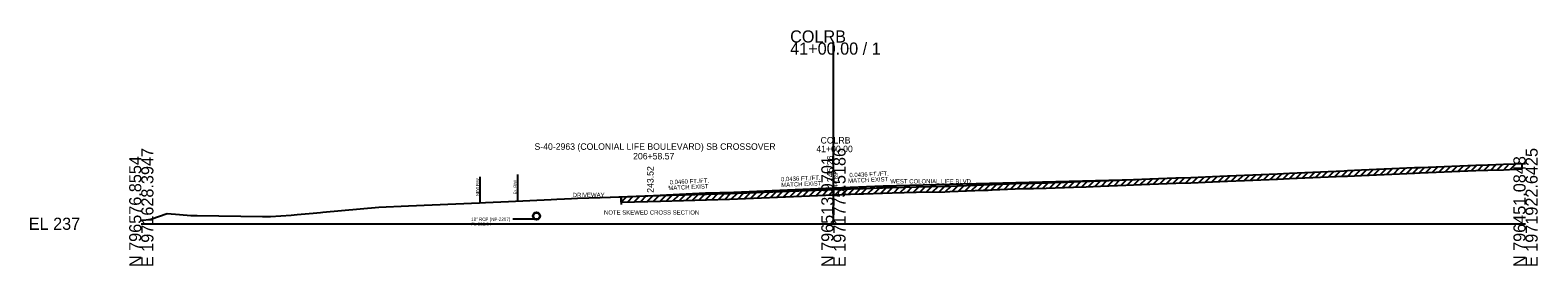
# Model space of a CAD drawing. Extents: x -26 to 1971766, y -10 to 796432.
# Drawn here: x -25.7 to 322.8, y 5490.3 to 5544.7 of the extents above; entities that cross this region are included whole.
import ezdxf

# ---------------------------------------------------------------- set-up
doc = ezdxf.new("R2010")
doc.units = 0
for name, color, linetype in [('BR_AUTO DIMENSION', 7, 'Continuous'), ('BR_BORDER LINES', 7, 'Continuous'), ('BR_CENTER LINE BASELINE', 7, 'Continuous'), ('BR_CONCRETE', 7, 'Continuous'), ('BR_TABLE LINES', 7, 'Continuous'), ('Level 31', 7, 'Continuous'), ('MISCELLANEOUS', 7, 'Continuous'), ('North Arrow', 7, 'Continuous'), ('RD_HC_CL_Rel', 7, 'Continuous'), ('RD_PD_ALT2_TnTmp', 7, 'Continuous'), ('RD_PD_CstnLmt', 7, 'Continuous'), ('RD_PD_FOC', 7, 'Continuous'), ('RD_PD_MedBWall', 7, 'Continuous'), ('RD_PD_WallFill', 7, 'Continuous'), ('RD_SHT_IplotShp', 7, 'Continuous')]:
    doc.layers.add(name, color=color, linetype=linetype)

msp = doc.modelspace()

# ---------------------------------------------------------------- linework, layer by layer
at = {"layer": 'BR_AUTO DIMENSION'}
for p, q in [((160, 5500), (160, 5541.81)), ((0, 5500), (160, 5500)), ((160, 5500), (320, 5500))]:
    msp.add_line(p, q, dxfattribs=at)
at = {"layer": 'BR_BORDER LINES'}
msp.add_lwpolyline([(0, 5500.79), (2.17, 5501.04), (6.01, 5502.35), (8.85, 5502.13), (11.47, 5501.89), (12.93, 5501.87), (28.02, 5501.69), (28.61, 5501.7), (29.89, 5501.7), (34.65, 5502), (36.03, 5502.11), (39.71, 5502.46), (41.42, 5502.59), (41.96, 5502.64), (54.91, 5503.82), (61.76, 5504.11), (78.16, 5504.83), (79.56, 5504.9), (84.88, 5505.14), (94.78, 5505.58), (96.06, 5505.65), (97.83, 5505.75), (99.44, 5505.83), (100.82, 5505.89), (106.04, 5506.05), (110.94, 5506.25), (117.06, 5506.42), (119.99, 5506.5), (135.94, 5506.95), (160, 5507.89), (165.93, 5508.12), (166.51, 5508.15), (166.96, 5508.17), (173.59, 5508.4), (179.16, 5508.51), (185.72, 5508.65), (186.9, 5508.69), (194.62, 5508.99), (195.79, 5509.04), (196.66, 5509.08), (203.77, 5509.36), (206.24, 5509.4), (209.18, 5509.47), (215.48, 5509.71), (218.45, 5509.8), (221.72, 5509.92), (227.57, 5510.15), (229.33, 5510.23), (233.15, 5510.35), (239.13, 5510.59), (242.65, 5510.7), (249.35, 5510.98), (251.06, 5511.04), (255.04, 5511.24), (262.63, 5511.55), (265.41, 5511.7), (274.39, 5512.07), (278.1, 5512.22), (278.86, 5512.26), (282.07, 5512.41), (294.35, 5512.95), (295.65, 5512.99), (308.47, 5513.54), (311.26, 5513.62), (314.9, 5513.73), (320, 5513.94)], dxfattribs=at)
at = {"layer": 'BR_CENTER LINE BASELINE'}
for p, q in [((319.14, 5513.9), (319.14, 5512.65)), ((255.04, 5509.99), (262.63, 5510.3)), ((262.63, 5510.3), (265.41, 5510.45)), ((265.41, 5510.45), (274.39, 5510.82)), ((274.39, 5510.82), (278.1, 5510.97)), ((278.1, 5510.97), (278.86, 5511.01)), ((278.86, 5511.01), (282.07, 5511.16)), ((282.07, 5511.16), (294.35, 5511.7)), ((294.35, 5511.7), (295.65, 5511.74)), ((295.65, 5511.74), (308.47, 5512.29)), ((308.47, 5512.29), (311.26, 5512.37)), ((311.26, 5512.37), (314.9, 5512.48)), ((314.9, 5512.48), (319.14, 5512.65)), ((160, 5506.64), (165.93, 5506.87)), ((165.93, 5506.87), (166.51, 5506.9)), ((166.51, 5506.9), (166.96, 5506.92)), ((166.96, 5506.92), (173.59, 5507.15)), ((173.59, 5507.15), (179.16, 5507.26)), ((179.16, 5507.26), (185.72, 5507.4)), ((185.72, 5507.4), (186.9, 5507.44)), ((186.9, 5507.44), (194.62, 5507.74)), ((194.62, 5507.74), (195.79, 5507.79)), ((195.79, 5507.79), (196.66, 5507.83)), ((196.66, 5507.83), (203.77, 5508.11)), ((203.77, 5508.11), (206.24, 5508.15)), ((206.24, 5508.15), (209.18, 5508.22)), ((209.18, 5508.22), (215.48, 5508.46)), ((215.48, 5508.46), (218.45, 5508.55)), ((218.45, 5508.55), (221.72, 5508.67)), ((221.72, 5508.67), (227.57, 5508.9)), ((227.57, 5508.9), (229.33, 5508.98)), ((229.33, 5508.98), (233.15, 5509.1)), ((233.15, 5509.1), (239.13, 5509.34)), ((239.13, 5509.34), (242.65, 5509.45)), ((242.65, 5509.45), (249.35, 5509.73)), ((249.35, 5509.73), (251.06, 5509.79)), ((251.06, 5509.79), (255.04, 5509.99)), ((110.94, 5505), (110.94, 5506.25)), ((110.94, 5505), (117.06, 5505.17)), ((117.06, 5505.17), (119.99, 5505.25)), ((119.99, 5505.25), (135.94, 5505.7)), ((135.94, 5505.7), (160, 5506.64))]:
    msp.add_line(p, q, dxfattribs=at)
at = {"layer": 'BR_TABLE LINES'}
msp.add_line((86.98, 5511.4), (86.98, 5505.4), dxfattribs=at)
at = {"layer": 'Level 31'}
for p, q in [((314.94, 5512.48), (316.24, 5513.79)), ((316.44, 5512.54), (317.74, 5513.85)), ((230.94, 5509.03), (232.23, 5510.32)), ((232.44, 5509.08), (233.74, 5510.37)), ((233.94, 5509.13), (235.24, 5510.43)), ((235.44, 5509.19), (236.74, 5510.49)), ((236.94, 5509.25), (238.24, 5510.55)), ((238.44, 5509.31), (239.74, 5510.61)), ((239.94, 5509.36), (241.23, 5510.66)), ((241.44, 5509.41), (242.73, 5510.7)), ((242.94, 5509.46), (244.25, 5510.77)), ((244.44, 5509.52), (245.75, 5510.83)), ((245.94, 5509.59), (247.25, 5510.89)), ((247.44, 5509.65), (248.75, 5510.95)), ((248.94, 5509.71), (250.24, 5511.01)), ((250.44, 5509.77), (251.75, 5511.07)), ((251.94, 5509.83), (253.26, 5511.15)), ((253.44, 5509.91), (254.76, 5511.22)), ((254.94, 5509.98), (256.25, 5511.29)), ((256.44, 5510.04), (257.75, 5511.35)), ((257.94, 5510.11), (259.25, 5511.41)), ((259.44, 5510.17), (260.75, 5511.48)), ((260.94, 5510.23), (262.25, 5511.54)), ((262.44, 5510.3), (263.76, 5511.61)), ((263.94, 5510.37), (265.26, 5511.69)), ((265.44, 5510.45), (266.75, 5511.75)), ((266.94, 5510.51), (268.25, 5511.81)), ((268.44, 5510.57), (269.75, 5511.87)), ((269.94, 5510.63), (271.25, 5511.94)), ((271.44, 5510.69), (272.75, 5512)), ((272.94, 5510.76), (274.25, 5512.06)), ((274.44, 5510.82), (275.75, 5512.12)), ((275.94, 5510.88), (277.25, 5512.19)), ((277.44, 5510.94), (278.75, 5512.25)), ((278.94, 5511.01), (280.26, 5512.33)), ((280.44, 5511.09), (281.76, 5512.4)), ((281.94, 5511.16), (283.25, 5512.47)), ((283.44, 5511.22), (284.75, 5512.53)), ((284.94, 5511.29), (286.25, 5512.6)), ((286.44, 5511.35), (287.75, 5512.66)), ((287.94, 5511.42), (289.25, 5512.73)), ((289.44, 5511.48), (290.75, 5512.79)), ((290.94, 5511.55), (292.25, 5512.86)), ((292.44, 5511.61), (293.75, 5512.92)), ((293.94, 5511.68), (295.24, 5512.98)), ((295.44, 5511.73), (296.75, 5513.04)), ((296.94, 5511.8), (298.25, 5513.1)), ((298.44, 5511.86), (299.75, 5513.16)), ((299.94, 5511.92), (301.25, 5513.23)), ((301.44, 5511.99), (302.75, 5513.29)), ((302.94, 5512.05), (304.25, 5513.36)), ((304.44, 5512.11), (305.75, 5513.42)), ((305.94, 5512.18), (307.25, 5513.48)), ((307.44, 5512.24), (308.74, 5513.54)), ((308.94, 5512.3), (310.23, 5513.59)), ((310.44, 5512.35), (311.73, 5513.64)), ((311.94, 5512.39), (313.23, 5513.68)), ((313.44, 5512.44), (314.73, 5513.73)), ((130.44, 5505.54), (131.73, 5506.83)), ((131.94, 5505.58), (133.23, 5506.87)), ((133.44, 5505.63), (134.73, 5506.91)), ((134.94, 5505.67), (136.23, 5506.96)), ((136.44, 5505.72), (137.74, 5507.02)), ((137.94, 5505.77), (139.24, 5507.08)), ((139.44, 5505.83), (140.74, 5507.13)), ((140.94, 5505.89), (142.24, 5507.19)), ((142.44, 5505.95), (143.74, 5507.25)), ((143.94, 5506.01), (145.24, 5507.31)), ((145.44, 5506.07), (146.74, 5507.37)), ((146.94, 5506.13), (148.24, 5507.43)), ((148.44, 5506.19), (149.74, 5507.49)), ((149.94, 5506.25), (151.24, 5507.55)), ((151.44, 5506.3), (152.74, 5507.61)), ((152.94, 5506.36), (154.24, 5507.66)), ((154.44, 5506.42), (155.74, 5507.72)), ((155.94, 5506.48), (157.24, 5507.78)), ((157.44, 5506.54), (158.74, 5507.84)), ((158.94, 5506.6), (160.24, 5507.9)), ((160.44, 5506.66), (161.74, 5507.96)), ((161.94, 5506.72), (163.24, 5508.02)), ((163.44, 5506.78), (164.74, 5508.08)), ((164.94, 5506.84), (166.24, 5508.14)), ((166.44, 5506.89), (167.74, 5508.19)), ((167.94, 5506.95), (169.24, 5508.25)), ((169.44, 5507), (170.74, 5508.3)), ((170.94, 5507.06), (172.24, 5508.35)), ((172.44, 5507.11), (173.74, 5508.41)), ((173.94, 5507.16), (175.22, 5508.43)), ((175.44, 5507.19), (176.72, 5508.46)), ((176.94, 5507.22), (178.22, 5508.49)), ((178.44, 5507.25), (179.72, 5508.52)), ((179.94, 5507.28), (181.22, 5508.55)), ((181.44, 5507.31), (182.72, 5508.58)), ((182.94, 5507.34), (184.22, 5508.62)), ((184.44, 5507.37), (185.72, 5508.65)), ((185.94, 5507.41), (187.24, 5508.7)), ((187.44, 5507.46), (188.74, 5508.76)), ((188.94, 5507.52), (190.24, 5508.82)), ((190.44, 5507.58), (191.74, 5508.88)), ((191.94, 5507.64), (193.24, 5508.94)), ((193.44, 5507.7), (194.74, 5509)), ((194.94, 5507.76), (196.25, 5509.06)), ((196.44, 5507.82), (197.74, 5509.12)), ((197.94, 5507.88), (199.24, 5509.18)), ((199.44, 5507.94), (200.74, 5509.24)), ((200.94, 5508), (202.24, 5509.3)), ((202.44, 5508.05), (203.74, 5509.35)), ((203.94, 5508.11), (205.21, 5509.38)), ((205.44, 5508.13), (206.72, 5509.41)), ((206.94, 5508.16), (208.22, 5509.44)), ((208.44, 5508.2), (209.73, 5509.49)), ((209.94, 5508.25), (211.24, 5509.55)), ((211.44, 5508.3), (212.74, 5509.6)), ((212.94, 5508.36), (214.24, 5509.66)), ((214.44, 5508.42), (215.74, 5509.72)), ((215.94, 5508.48), (217.23, 5509.76)), ((217.44, 5508.52), (218.73, 5509.81)), ((218.94, 5508.57), (220.24, 5509.87)), ((220.44, 5508.63), (221.74, 5509.92)), ((221.94, 5508.68), (223.24, 5509.98)), ((223.44, 5508.74), (224.74, 5510.04)), ((224.94, 5508.8), (226.24, 5510.1)), ((226.44, 5508.86), (227.74, 5510.16)), ((227.94, 5508.92), (229.25, 5510.23)), ((229.44, 5508.98), (230.73, 5510.27)), ((110.94, 5505), (112.23, 5506.29)), ((112.44, 5505.04), (113.73, 5506.33)), ((113.94, 5505.09), (115.23, 5506.37)), ((115.44, 5505.13), (116.73, 5506.42)), ((116.94, 5505.17), (118.22, 5506.45)), ((118.44, 5505.21), (119.72, 5506.49)), ((119.94, 5505.25), (121.23, 5506.53)), ((121.44, 5505.29), (122.73, 5506.58)), ((122.94, 5505.33), (124.23, 5506.62)), ((124.44, 5505.37), (125.73, 5506.66)), ((125.94, 5505.42), (127.23, 5506.7)), ((127.44, 5505.46), (128.73, 5506.74)), ((128.94, 5505.5), (130.23, 5506.79))]:
    msp.add_line(p, q, dxfattribs=at)
at = {"layer": 'MISCELLANEOUS'}
for p, q in [((119.99, 5506.5), (135.94, 5506.95)), ((135.94, 5506.95), (160, 5507.89)), ((160, 5507.89), (165.93, 5508.12)), ((165.93, 5508.12), (166.51, 5508.15)), ((166.51, 5508.15), (166.96, 5508.17)), ((166.96, 5508.17), (171.47, 5508.33)), ((171.47, 5508.33), (173.59, 5508.4)), ((173.59, 5508.4), (179.16, 5508.51)), ((179.16, 5508.51), (182.44, 5508.58)), ((182.44, 5508.58), (186.31, 5508.67)), ((186.31, 5508.67), (190.76, 5508.84)), ((190.76, 5508.84), (200.22, 5509.22)), ((200.22, 5509.22), (203.77, 5509.36)), ((203.77, 5509.36), (209.18, 5509.47)), ((209.18, 5509.47), (212.33, 5509.59)), ((212.33, 5509.59), (216.96, 5509.76)), ((216.96, 5509.76), (221.72, 5509.92)), ((221.72, 5509.92), (224.65, 5510.04)), ((224.65, 5510.04), (229.85, 5510.25)), ((110.94, 5506.25), (117.06, 5506.42)), ((110.94, 5506.25), (110.94, 5504.41)), ((117.06, 5506.42), (119.99, 5506.5))]:
    msp.add_line(p, q, dxfattribs=at)
at = {"layer": 'North Arrow'}
for p, q in [((118.42, 5506.52), (130.45, 5507.15)), ((137, 5507.26), (160, 5508.26)), ((160, 5508.26), (171.47, 5508.76)), ((171.47, 5508.76), (229.85, 5510.25)), ((106.38, 5506.06), (118.42, 5506.52))]:
    msp.add_line(p, q, dxfattribs=at)
at = {"layer": 'RD_PD_CstnLmt'}
msp.add_line((78.29, 5510.85), (78.29, 5504.85), dxfattribs=at)
at = {"layer": 'RD_PD_FOC'}
msp.add_line((90.88, 5501.04), (85.88, 5501.04), dxfattribs=at)
for radius in [0.85, 0.75]:
    msp.add_circle((91.38, 5501.79), radius, dxfattribs=at)
at = {"layer": 'RD_PD_MedBWall'}
msp.add_line((130.45, 5507.15), (137, 5507.26), dxfattribs=at)

# ---------------------------------------------------------------- texts
at = {"layer": 'BR_AUTO DIMENSION'}
for s, p in [('41+00.00 / 1', (150, 5539.01)), ('COLRB', (150, 5541.81)), ('EL 237', (-26, 5498.6))]:
    msp.add_text(s, height=2.8, dxfattribs=at).set_placement(p)
for s, p in [('E 1971628.3947', (2.8, 5490)), ('E 1971775.5186', (162.8, 5490)), ('E 1971922.6425', (322.8, 5490)), ('N 796576.8554', (0, 5490)), ('N 796513.9701', (160, 5490)), ('N 796451.0848', (320, 5490))]:
    msp.add_text(s, height=2.8, rotation=90, dxfattribs=at).set_placement(p)
at = {"layer": 'BR_CONCRETE'}
for s, rotation, p in [('0.0460 FT./FT.', 2.6332, (122.16, 5509.08)), ('0.0436 FT./FT.', 2.4965, (147.9, 5509.77)), ('MATCH EXIST', 2.4959, (163.41, 5509.41)), ('0.0436 FT./FT.', 2.4959, (163.71, 5510.73)), ('MATCH EXIST', 2.6332, (121.86, 5507.75)), ('MATCH EXIST', 2.4965, (147.96, 5508.46))]:
    msp.add_text(s, height=1, rotation=rotation, dxfattribs=at).set_placement(p)
at = {"layer": 'BR_TABLE LINES'}
msp.add_text('Ex. R/W ', height=0.65, rotation=90, dxfattribs=at).set_placement((86.73, 5506.78))
at = {"layer": 'RD_HC_CL_Rel'}
for s, p in [('245.26', (160, 5509.6)), (' 243.52', (118.42, 5506.59))]:
    msp.add_text(s, height=1.5, rotation=90, dxfattribs=at).set_placement(p)
at = {"layer": 'RD_PD_ALT2_TnTmp'}
for s, p in [('WEST COLONIAL LIFE BLVD.', (173.15, 5509.3)), ('DRIVEWAY', (99.73, 5506.14)), ('NOTE SKEWED CROSS SECTION', (106.96, 5502.11))]:
    msp.add_text(s, height=1, dxfattribs=at).set_placement(p)
at = {"layer": 'RD_PD_CstnLmt'}
msp.add_text('NEW R/W ', height=0.65, rotation=90, dxfattribs=at).set_placement((78.03, 5506.41))
at = {"layer": 'RD_PD_FOC'}
for s, p in [('18" RCP (NP-2207)', (76.25, 5500.67)), ('FL 238.04', (76.25, 5499.54))]:
    msp.add_text(s, height=0.75, dxfattribs=at).set_placement(p)
at = {"layer": 'RD_PD_WallFill'}
for s, p in [('S-40-2963 (COLONIAL LIFE BOULEVARD) SB CROSSOVER', (90.9, 5517.06)), ('41+00.00', (156.05, 5516.51)), ('COLRB', (157.03, 5518.51)), ('206+58.57', (113.69, 5514.84))]:
    msp.add_text(s, height=1.5, dxfattribs=at).set_placement(p)
at = {"layer": 'RD_SHT_IplotShp'}
msp.add_text('244.89', height=1, rotation=90, dxfattribs=at).set_placement((161, 5507.56))

doc.saveas('drawing.dxf')
